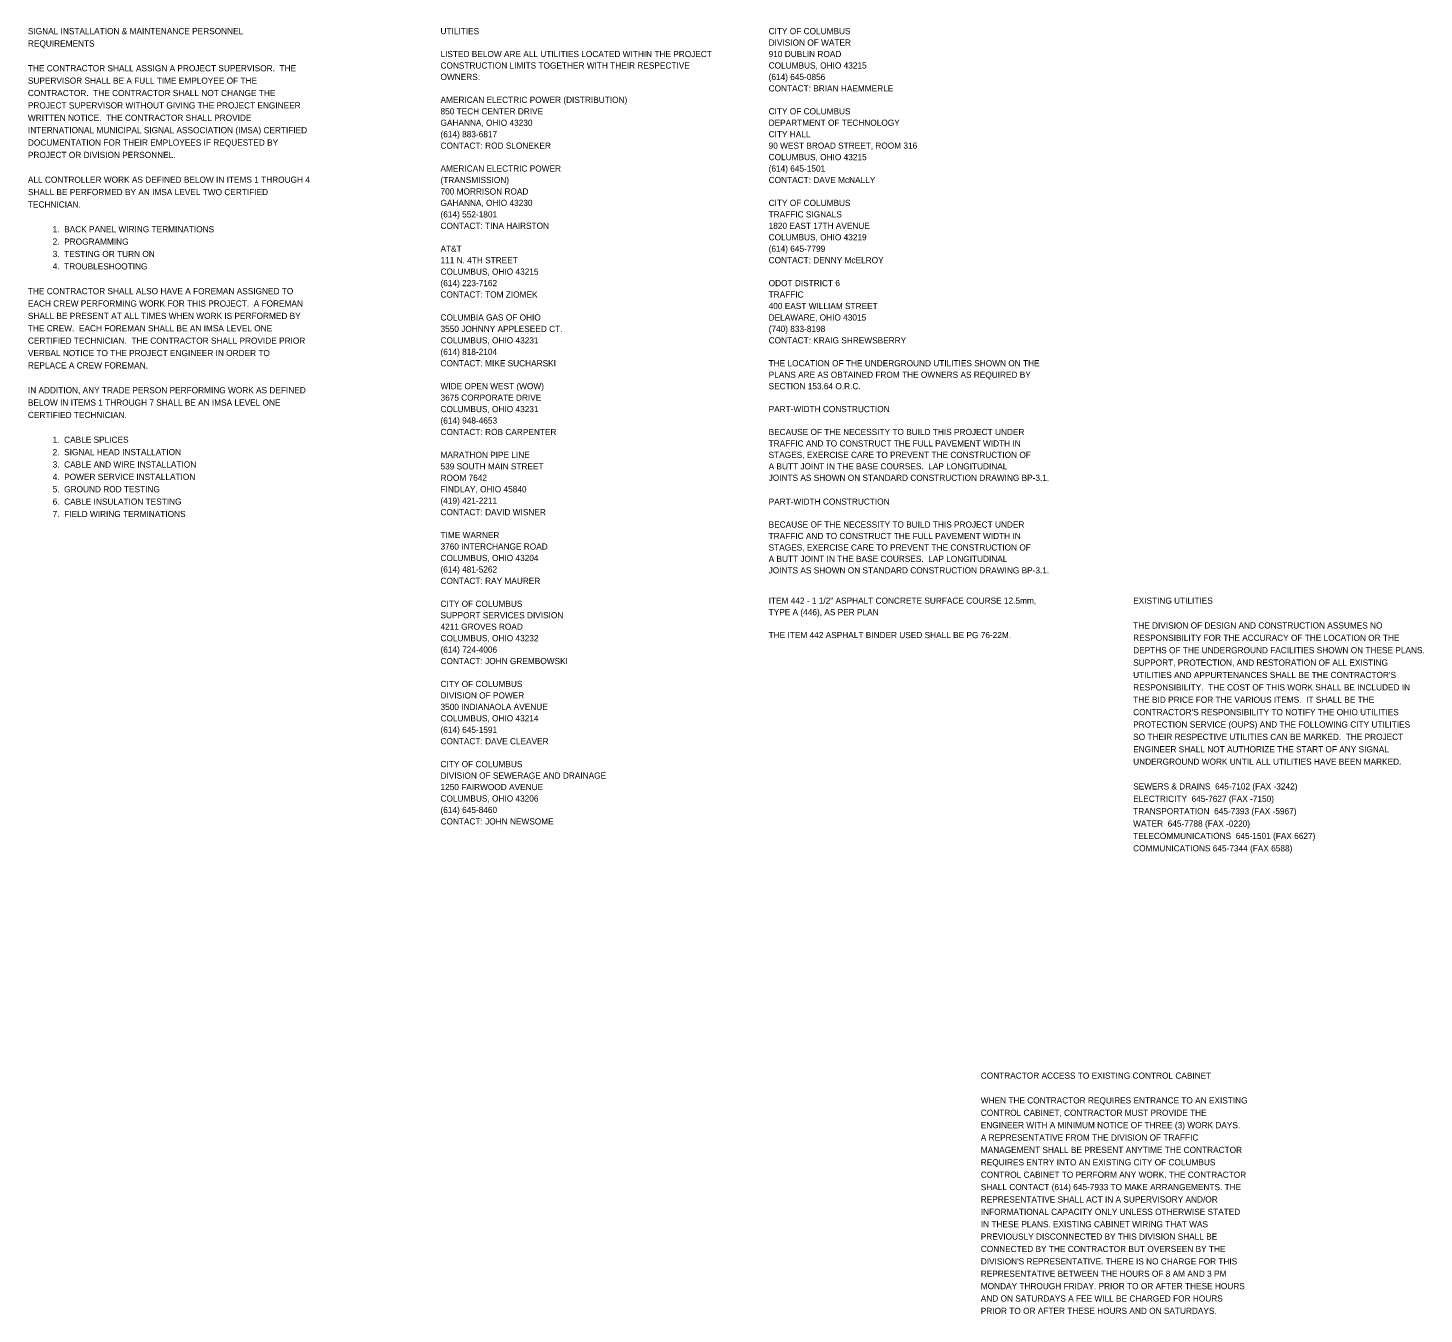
# Model space of a CAD drawing. Extents: x -62 to 50, y -16 to 14.
# Drawn here: x -34.97 to -3.4, y -15.45 to 13.63 of the extents above; entities that cross this region are included whole.
import ezdxf

# ---------------------------------------------------------------- set-up
doc = ezdxf.new("R2010")
doc.units = 0
for name, color, linetype in [('SH_Data', 7, 'Continuous'), ('SH_Text', 7, 'Continuous'), ('TX_P_50', 7, 'Continuous')]:
    doc.layers.add(name, color=color, linetype=linetype)

msp = doc.modelspace()

# ---------------------------------------------------------------- texts
at = {"layer": 'SH_Data'}
for s, p in [('CONTRACTOR ACCESS TO EXISTING CONTROL CABINET', (-13.423, -10.128)), ('WHEN THE CONTRACTOR REQUIRES ENTRANCE TO AN EXISTING ', (-13.423, -10.688)), ('CONTROL CABINET, CONTRACTOR MUST PROVIDE THE ', (-13.423, -10.968)), ('ENGINEER WITH A MINIMUM NOTICE OF THREE (3) WORK DAYS. ', (-13.423, -11.248)), ('A REPRESENTATIVE FROM THE DIVISION OF TRAFFIC ', (-13.423, -11.528)), ('MANAGEMENT SHALL BE PRESENT ANYTIME THE CONTRACTOR ', (-13.423, -11.808)), ('REQUIRES ENTRY INTO AN EXISTING CITY OF COLUMBUS ', (-13.423, -12.088)), ('CONTROL CABINET TO PERFORM ANY WORK. THE CONTRACTOR ', (-13.423, -12.368)), ('SHALL CONTACT (614) 645-7933 TO MAKE ARRANGEMENTS. THE ', (-13.423, -12.648)), ('REPRESENTATIVE SHALL ACT IN A SUPERVISORY AND/OR ', (-13.423, -12.928)), ('INFORMATIONAL CAPACITY ONLY UNLESS OTHERWISE STATED ', (-13.423, -13.208)), ('IN THESE PLANS. EXISTING CABINET WIRING THAT WAS ', (-13.423, -13.488)), ('PREVIOUSLY DISCONNECTED BY THIS DIVISION SHALL BE ', (-13.423, -13.768)), ('CONNECTED BY THE CONTRACTOR BUT OVERSEEN BY THE ', (-13.423, -14.048)), ("DIVISION'S REPRESENTATIVE. THERE IS NO CHARGE FOR THIS ", (-13.423, -14.328)), ('REPRESENTATIVE BETWEEN THE HOURS OF 8 AM AND 3 PM ', (-13.423, -14.608)), ('MONDAY THROUGH FRIDAY. PRIOR TO OR AFTER THESE HOURS ', (-13.423, -14.888)), ('AND ON SATURDAYS A FEE WILL BE CHARGED FOR HOURS ', (-13.423, -15.168)), ('PRIOR TO OR AFTER THESE HOURS AND ON SATURDAYS. ', (-13.423, -15.448))]:
    msp.add_text(s, height=0.14, dxfattribs=at).set_placement(p)
at = {"layer": 'SH_Text'}
for s, p in [('SIGNAL INSTALLATION & MAINTENANCE PERSONNEL ', (-34.97, 13.492)), ('CITY OF COLUMBUS ', (-18.22, 13.492)), ('REQUIREMENTS', (-34.97, 13.212)), ('DIVISION OF WATER', (-18.22, 13.233)), ('910 DUBLIN ROAD', (-18.22, 12.974)), ('THE CONTRACTOR SHALL ASSIGN A PROJECT SUPERVISOR.  THE ', (-34.97, 12.652)), ('COLUMBUS, OHIO 43215', (-18.22, 12.715)), ('SUPERVISOR SHALL BE A FULL TIME EMPLOYEE OF THE ', (-34.97, 12.372)), ('CONTACT: BRIAN HAEMMERLE', (-18.22, 12.197)), ('(614) 645-0856', (-18.22, 12.456)), ('CONTRACTOR.  THE CONTRACTOR SHALL NOT CHANGE THE ', (-34.97, 12.092)), ('PROJECT SUPERVISOR WITHOUT GIVING THE PROJECT ENGINEER ', (-34.97, 11.812)), ('CITY OF COLUMBUS ', (-18.22, 11.679)), ('WRITTEN NOTICE.  THE CONTRACTOR SHALL PROVIDE ', (-34.97, 11.532)), ('INTERNATIONAL MUNICIPAL SIGNAL ASSOCIATION (IMSA) CERTIFIED ', (-34.97, 11.252)), ('DEPARTMENT OF TECHNOLOGY', (-18.22, 11.42)), ('DOCUMENTATION FOR THEIR EMPLOYEES IF REQUESTED BY ', (-34.97, 10.972)), ('CITY HALL', (-18.22, 11.161)), ('PROJECT OR DIVISION PERSONNEL.', (-34.97, 10.692)), ('90 WEST BROAD STREET, ROOM 316', (-18.22, 10.902)), ('COLUMBUS, OHIO 43215', (-18.22, 10.643)), ('(614) 645-1501', (-18.22, 10.384)), ('ALL CONTROLLER WORK AS DEFINED BELOW IN ITEMS 1 THROUGH 4 ', (-34.97, 10.132)), ('CONTACT: DAVE McNALLY', (-18.22, 10.125)), ('SHALL BE PERFORMED BY AN IMSA LEVEL TWO CERTIFIED ', (-34.97, 9.852)), ('TECHNICIAN.', (-34.97, 9.572)), ('TRAFFIC SIGNALS', (-18.22, 9.348)), ('CITY OF COLUMBUS', (-18.22, 9.607)), ('1820 EAST 17TH AVENUE', (-18.22, 9.089)), ('2.  PROGRAMMING', (-34.41, 8.732)), ('1.  BACK PANEL WIRING TERMINATIONS', (-34.41, 9.012)), ('COLUMBUS, OHIO 43219', (-18.22, 8.83)), ('3.  TESTING OR TURN ON', (-34.41, 8.452)), ('(614) 645-7799', (-18.22, 8.571)), ('4.  TROUBLESHOOTING', (-34.41, 8.172)), ('CONTACT: DENNY McELROY', (-18.22, 8.312)), ('ODOT DISTRICT 6', (-18.22, 7.794)), ('THE CONTRACTOR SHALL ALSO HAVE A FOREMAN ASSIGNED TO ', (-34.97, 7.612)), ('TRAFFIC', (-18.22, 7.535)), ('EACH CREW PERFORMING WORK FOR THIS PROJECT.  A FOREMAN ', (-34.97, 7.332)), ('400 EAST WILLIAM STREET', (-18.22, 7.276)), ('SHALL BE PRESENT AT ALL TIMES WHEN WORK IS PERFORMED BY ', (-34.97, 7.052)), ('DELAWARE, OHIO 43015', (-18.22, 7.017)), ('THE CREW.  EACH FOREMAN SHALL BE AN IMSA LEVEL ONE ', (-34.97, 6.772)), ('CERTIFIED TECHNICIAN.  THE CONTRACTOR SHALL PROVIDE PRIOR ', (-34.97, 6.492)), ('CONTACT: KRAIG SHREWSBERRY', (-18.22, 6.499)), ('(740) 833-8198', (-18.22, 6.758)), ('VERBAL NOTICE TO THE PROJECT ENGINEER IN ORDER TO ', (-34.97, 6.212)), ('REPLACE A CREW FOREMAN.', (-34.97, 5.932)), ('THE LOCATION OF THE UNDERGROUND UTILITIES SHOWN ON THE', (-18.22, 5.981)), ('PLANS ARE AS OBTAINED FROM THE OWNERS AS REQUIRED BY', (-18.22, 5.722)), ('IN ADDITION, ANY TRADE PERSON PERFORMING WORK AS DEFINED ', (-34.97, 5.372)), ('SECTION 153.64 O.R.C.', (-18.22, 5.463)), ('BELOW IN ITEMS 1 THROUGH 7 SHALL BE AN IMSA LEVEL ONE ', (-34.97, 5.092)), ('PART-WIDTH CONSTRUCTION', (-18.22, 4.945)), ('CERTIFIED TECHNICIAN.', (-34.97, 4.812)), ('BECAUSE OF THE NECESSITY TO BUILD THIS PROJECT UNDER', (-18.22, 4.427)), ('2.  SIGNAL HEAD INSTALLATION', (-34.41, 3.972)), ('1.  CABLE SPLICES', (-34.41, 4.252)), ('TRAFFIC AND TO CONSTRUCT THE FULL PAVEMENT WIDTH IN', (-18.22, 4.168)), ('3.  CABLE AND WIRE INSTALLATION', (-34.41, 3.692)), ('A BUTT JOINT IN THE BASE COURSES.  LAP LONGITUDINAL', (-18.22, 3.65)), ('STAGES, EXERCISE CARE TO PREVENT THE CONSTRUCTION OF', (-18.22, 3.909)), ('4.  POWER SERVICE INSTALLATION', (-34.41, 3.412)), ('JOINTS AS SHOWN ON STANDARD CONSTRUCTION DRAWING BP-3.1.', (-18.22, 3.391)), ('5.  GROUND ROD TESTING', (-34.41, 3.132)), ('6.  CABLE INSULATION TESTING', (-34.41, 2.852)), ('PART-WIDTH CONSTRUCTION', (-18.22, 2.852)), ('7.  FIELD WIRING TERMINATIONS', (-34.41, 2.572)), ('TRAFFIC AND TO CONSTRUCT THE FULL PAVEMENT WIDTH IN', (-18.22, 2.075)), ('BECAUSE OF THE NECESSITY TO BUILD THIS PROJECT UNDER', (-18.22, 2.334)), ('STAGES, EXERCISE CARE TO PREVENT THE CONSTRUCTION OF', (-18.22, 1.816)), ('A BUTT JOINT IN THE BASE COURSES.  LAP LONGITUDINAL', (-18.22, 1.557)), ('JOINTS AS SHOWN ON STANDARD CONSTRUCTION DRAWING BP-3.1.', (-18.22, 1.298)), ('ITEM 442 - 1 1/2" ASPHALT CONCRETE SURFACE COURSE 12.5mm, ', (-18.22, 0.612)), ('EXISTING UTILITIES ', (-9.977, 0.612)), ('TYPE A (446), AS PER PLAN', (-18.22, 0.353)), ('THE DIVISION OF DESIGN AND CONSTRUCTION ASSUMES NO ', (-9.977, 0.052)), ('THE ITEM 442 ASPHALT BINDER USED SHALL BE PG 76-22M.', (-18.22, -0.165)), ('RESPONSIBILITY FOR THE ACCURACY OF THE LOCATION OR THE ', (-9.977, -0.228)), ('DEPTHS OF THE UNDERGROUND FACILITIES SHOWN ON THESE PLANS.  ', (-9.977, -0.508)), ('SUPPORT, PROTECTION, AND RESTORATION OF ALL EXISTING ', (-9.977, -0.788)), ("UTILITIES AND APPURTENANCES SHALL BE THE CONTRACTOR'S ", (-9.977, -1.068)), ('RESPONSIBILITY.  THE COST OF THIS WORK SHALL BE INCLUDED IN ', (-9.977, -1.348)), ('THE BID PRICE FOR THE VARIOUS ITEMS.  IT SHALL BE THE ', (-9.977, -1.628)), ("CONTRACTOR'S RESPONSIBILITY TO NOTIFY THE OHIO UTILITIES ", (-9.977, -1.908)), ('PROTECTION SERVICE (OUPS) AND THE FOLLOWING CITY UTILITIES ', (-9.977, -2.188)), ('SO THEIR RESPECTIVE UTILITIES CAN BE MARKED.  THE PROJECT ', (-9.977, -2.468)), ('ENGINEER SHALL NOT AUTHORIZE THE START OF ANY SIGNAL ', (-9.977, -2.748)), ('UNDERGROUND WORK UNTIL ALL UTILITIES HAVE BEEN MARKED.', (-9.977, -3.028)), ('SEWERS & DRAINS  645-7102 (FAX -3242)', (-9.977, -3.588)), ('ELECTRICITY  645-7627 (FAX -7150)', (-9.977, -3.868)), ('TRANSPORTATION  645-7393 (FAX -5967)', (-9.977, -4.148)), ('WATER  645-7788 (FAX -0220)', (-9.977, -4.428)), ('TELECOMMUNICATIONS  645-1501 (FAX 6627)', (-9.977, -4.708)), ('COMMUNICATIONS 645-7344 (FAX 6588)', (-9.977, -4.988))]:
    msp.add_text(s, height=0.14, dxfattribs=at).set_placement(p)
at = {"layer": 'TX_P_50'}
for s, p in [('UTILITIES', (-25.64, 13.492)), ('LISTED BELOW ARE ALL UTILITIES LOCATED WITHIN THE PROJECT', (-25.64, 12.974)), ('CONSTRUCTION LIMITS TOGETHER WITH THEIR RESPECTIVE', (-25.64, 12.715)), ('OWNERS: ', (-25.64, 12.456)), ('AMERICAN ELECTRIC POWER (DISTRIBUTION)', (-25.64, 11.938)), ('850 TECH CENTER DRIVE', (-25.64, 11.679)), ('GAHANNA, OHIO 43230', (-25.64, 11.42)), ('(614) 883-6817', (-25.64, 11.161)), ('CONTACT: ROD SLONEKER', (-25.64, 10.902)), ('AMERICAN ELECTRIC POWER', (-25.64, 10.384)), ('(TRANSMISSION)', (-25.64, 10.125)), ('700 MORRISON ROAD', (-25.64, 9.866)), ('GAHANNA, OHIO 43230', (-25.64, 9.607)), ('(614) 552-1801', (-25.64, 9.348)), ('CONTACT: TINA HAIRSTON', (-25.64, 9.089)), ('AT&T ', (-25.64, 8.571)), ('111 N. 4TH STREET', (-25.64, 8.312)), ('COLUMBUS, OHIO 43215', (-25.64, 8.053)), ('(614) 223-7162', (-25.64, 7.794)), ('CONTACT: TOM ZIOMEK', (-25.64, 7.535)), ('COLUMBIA GAS OF OHIO', (-25.64, 7.017)), ('3550 JOHNNY APPLESEED CT.', (-25.64, 6.758)), ('COLUMBUS, OHIO 43231', (-25.64, 6.499)), ('(614) 818-2104', (-25.64, 6.24)), ('CONTACT: MIKE SUCHARSKI', (-25.64, 5.981)), ('WIDE OPEN WEST (WOW)', (-25.64, 5.463)), ('3675 CORPORATE DRIVE', (-25.64, 5.204)), ('COLUMBUS, OHIO 43231', (-25.64, 4.945)), ('(614) 948-4653', (-25.64, 4.686)), ('CONTACT: ROB CARPENTER', (-25.64, 4.427)), ('539 SOUTH MAIN STREET', (-25.64, 3.65)), ('MARATHON PIPE LINE', (-25.64, 3.909)), ('ROOM 7642', (-25.64, 3.391)), ('FINDLAY, OHIO 45840', (-25.64, 3.132)), ('(419) 421-2211', (-25.64, 2.873)), ('CONTACT: DAVID WISNER', (-25.64, 2.614)), ('TIME WARNER', (-25.64, 2.096)), ('3760 INTERCHANGE ROAD', (-25.64, 1.837)), ('COLUMBUS, OHIO 43204', (-25.64, 1.578)), ('(614) 481-5262', (-25.64, 1.319)), ('CONTACT: RAY MAURER', (-25.64, 1.06)), ('CITY OF COLUMBUS', (-25.64, 0.542)), ('SUPPORT SERVICES DIVISION', (-25.64, 0.283)), ('4211 GROVES ROAD', (-25.64, 0.024)), ('COLUMBUS, OHIO 43232', (-25.64, -0.235)), ('CONTACT: JOHN GREMBOWSKI', (-25.64, -0.753)), ('(614) 724-4006', (-25.64, -0.494)), ('CITY OF COLUMBUS ', (-25.64, -1.271)), ('DIVISION OF POWER', (-25.64, -1.53)), ('3500 INDIANAOLA AVENUE', (-25.64, -1.789)), ('COLUMBUS, OHIO 43214', (-25.64, -2.048)), ('(614) 645-1591', (-25.64, -2.307)), ('CONTACT: DAVE CLEAVER', (-25.64, -2.566)), ('CITY OF COLUMBUS', (-25.64, -3.084)), ('1250 FAIRWOOD AVENUE', (-25.64, -3.602)), ('DIVISION OF SEWERAGE AND DRAINAGE', (-25.64, -3.343)), ('COLUMBUS, OHIO 43206', (-25.64, -3.861)), ('(614) 645-8460', (-25.64, -4.12)), ('CONTACT: JOHN NEWSOME', (-25.64, -4.379))]:
    msp.add_text(s, height=0.14, dxfattribs=at).set_placement(p)

doc.saveas('drawing.dxf')
